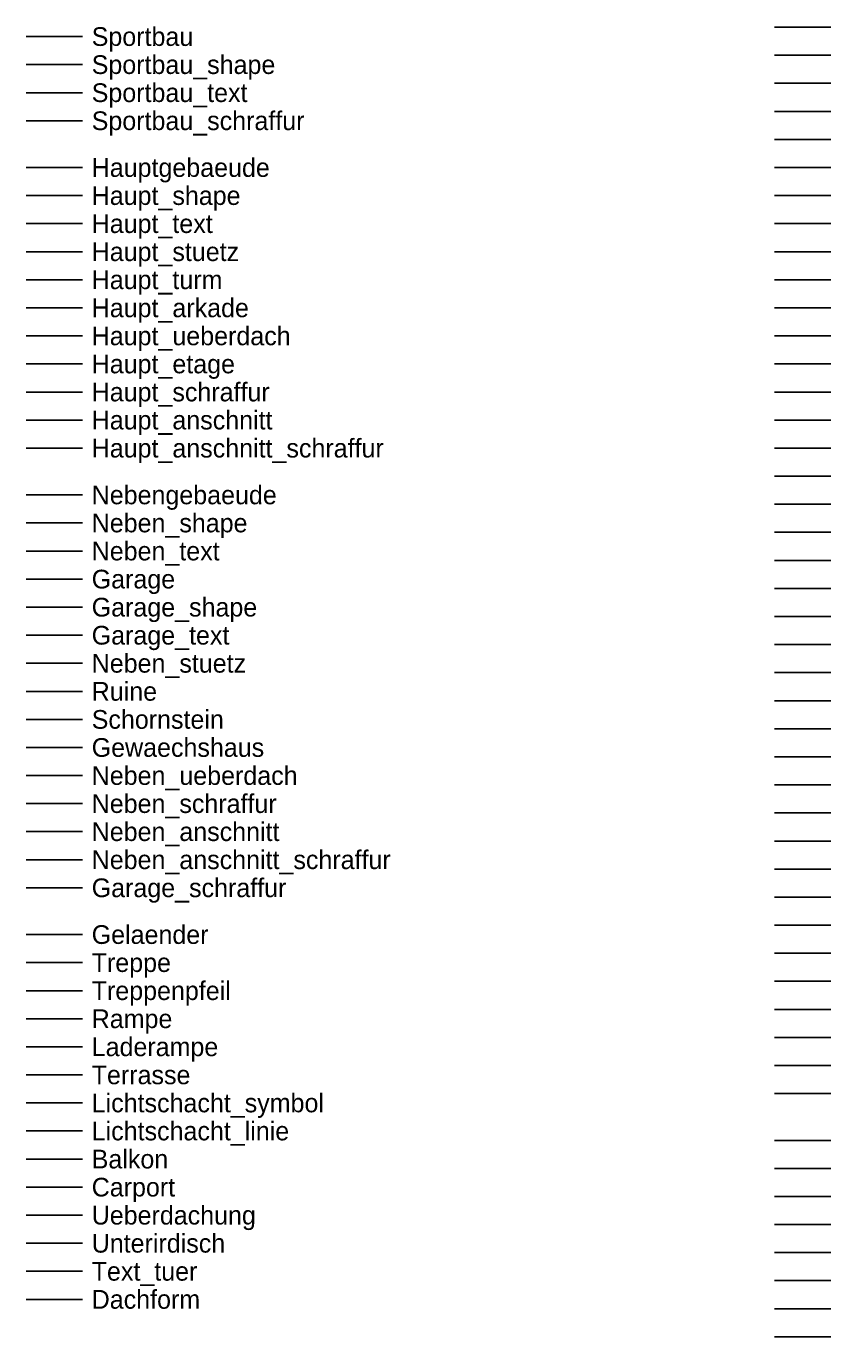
# Model space of a CAD drawing. Extents: x 0 to 177, y -135 to 1.
# Drawn here: x 0 to 43, y -134.5 to -64.4 of the extents above; entities that cross this region are included whole.
import ezdxf

# ---------------------------------------------------------------- set-up
doc = ezdxf.new("R2010")
doc.units = 0
for name, color, linetype in [('Anschlagsaeule', 7, 'Continuous'), ('Balkon', 7, 'Continuous'), ('Bank_linie', 7, 'Continuous'), ('Bank_symbol', 7, 'Continuous'), ('Befliegung_symbol', 7, 'Continuous'), ('Brandmelder', 7, 'Continuous'), ('Briefkasten', 7, 'Continuous'), ('Carport', 7, 'Continuous'), ('Dachform', 7, 'Continuous'), ('Denkmal', 7, 'Continuous'), ('Fahnenstange', 7, 'Continuous'), ('Fahrradstaender_linie', 7, 'Continuous'), ('Fahrradstaender_symbol', 7, 'Continuous'), ('Feuermelder', 7, 'Continuous'), ('Garage', 7, 'Continuous'), ('Garage_schraffur', 7, 'Continuous'), ('Garage_shape', 7, 'Continuous'), ('Garage_text', 7, 'Continuous'), ('Gelaender', 7, 'Continuous'), ('Gewaechshaus', 7, 'Continuous'), ('Haupt_anschnitt', 7, 'Continuous'), ('Haupt_anschnitt_schraffur', 7, 'Continuous'), ('Haupt_arkade', 7, 'Continuous'), ('Haupt_etage', 7, 'Continuous'), ('Haupt_schraffur', 7, 'Continuous'), ('Haupt_shape', 7, 'Continuous'), ('Haupt_stuetz', 7, 'Continuous'), ('Haupt_text', 7, 'Continuous'), ('Haupt_turm', 7, 'Continuous'), ('Haupt_ueberdach', 7, 'Continuous'), ('Hauptgebaeude', 7, 'Continuous'), ('Kaugummi', 7, 'Continuous'), ('Kilometerstein', 7, 'Continuous'), ('Kunst_linie', 7, 'Continuous'), ('Laderampe', 7, 'Continuous'), ('Leitpfosten', 7, 'Continuous'), ('Lichtschacht_linie', 7, 'Continuous'), ('Lichtschacht_symbol', 7, 'Continuous'), ('Mast_beton', 7, 'Continuous'), ('Mast_holz', 7, 'Continuous'), ('Mast_stahlgitter', 7, 'Continuous'), ('Mast_stahlrohr', 7, 'Continuous'), ('Merkstein', 7, 'Continuous'), ('Neben_anschnitt', 7, 'Continuous'), ('Neben_anschnitt_schraffur', 7, 'Continuous'), ('Neben_schraffur', 7, 'Continuous'), ('Neben_shape', 7, 'Continuous'), ('Neben_stuetz', 7, 'Continuous'), ('Neben_text', 7, 'Continuous'), ('Neben_ueberdach', 7, 'Continuous'), ('Nebengebaeude', 7, 'Continuous'), ('Notrufsaeule', 7, 'Continuous'), ('Ortstafel', 7, 'Continuous'), ('Papier_eckig', 7, 'Continuous'), ('Papier_rund', 7, 'Continuous'), ('Pfosten_beton', 7, 'Continuous'), ('Pfosten_holz', 7, 'Continuous'), ('Pfosten_metall', 7, 'Continuous'), ('Poller_eckig', 7, 'Continuous'), ('Poller_rund', 7, 'Continuous'), ('Rampe', 7, 'Continuous'), ('Ruine', 7, 'Continuous'), ('Schaltschrank', 7, 'Continuous'), ('Schieber', 7, 'Continuous'), ('Schildbruecke_linie', 7, 'Continuous'), ('Schildbruecke_symbol', 7, 'Continuous'), ('Schornstein', 7, 'Continuous'), ('Schranke_linie', 7, 'Continuous'), ('Schranke_symbol', 7, 'Continuous'), ('Sportbau', 7, 'Continuous'), ('Sportbau_schraffur', 7, 'Continuous'), ('Sportbau_shape', 7, 'Continuous'), ('Sportbau_text', 7, 'Continuous'), ('Terrasse', 7, 'Continuous'), ('Text_tuer', 7, 'Continuous'), ('Torpfosten_linie', 7, 'Continuous'), ('Treppe', 7, 'Continuous'), ('Treppenpfeil', 7, 'Continuous'), ('Ueberdachung', 7, 'Continuous'), ('Uhr', 7, 'Continuous'), ('Unterirdisch', 7, 'Continuous'), ('Verkehrszeichen', 7, 'Continuous'), ('Wegweiser', 7, 'Continuous'), ('Wegweiser_bel', 7, 'Continuous'), ('Werbetafel_linie', 7, 'Continuous'), ('Werbetafel_symbol', 7, 'Continuous'), ('Zaun_holz', 7, 'Continuous'), ('Zaun_metall', 7, 'Continuous'), ('Zaun_plaste', 7, 'Continuous'), ('Zauntor_text', 7, 'Continuous'), ('Zigaretten', 7, 'Continuous')]:
    doc.layers.add(name, color=color, linetype=linetype)

msp = doc.modelspace()

# ---------------------------------------------------------------- linework, layer by layer
at = {"layer": 'Anschlagsaeule'}
msp.add_line((40, -114), (43, -114), dxfattribs=at)
at = {"layer": 'Balkon'}
msp.add_line((0, -125), (3, -125), dxfattribs=at)
at = {"layer": 'Bank_linie'}
msp.add_line((40, -102), (43, -102), dxfattribs=at)
at = {"layer": 'Bank_symbol'}
msp.add_line((40, -100.5), (43, -100.5), dxfattribs=at)
at = {"layer": 'Befliegung_symbol'}
msp.add_line((40, -66), (43, -66), dxfattribs=at)
at = {"layer": 'Brandmelder'}
msp.add_line((40, -120), (43, -120), dxfattribs=at)
at = {"layer": 'Briefkasten'}
msp.add_line((40, -106.5), (43, -106.5), dxfattribs=at)
at = {"layer": 'Carport'}
msp.add_line((0, -126.5), (3, -126.5), dxfattribs=at)
at = {"layer": 'Dachform'}
msp.add_line((0, -132.5), (3, -132.5), dxfattribs=at)
at = {"layer": 'Denkmal'}
msp.add_line((40, -96), (43, -96), dxfattribs=at)
at = {"layer": 'Fahnenstange'}
msp.add_line((40, -79.5), (43, -79.5), dxfattribs=at)
at = {"layer": 'Fahrradstaender_linie'}
msp.add_line((40, -111), (43, -111), dxfattribs=at)
at = {"layer": 'Fahrradstaender_symbol'}
msp.add_line((40, -112.5), (43, -112.5), dxfattribs=at)
at = {"layer": 'Feuermelder'}
msp.add_line((40, -118.5), (43, -118.5), dxfattribs=at)
at = {"layer": 'Garage'}
msp.add_line((0, -94), (3, -94), dxfattribs=at)
at = {"layer": 'Garage_schraffur'}
msp.add_line((0, -110.5), (3, -110.5), dxfattribs=at)
at = {"layer": 'Garage_shape'}
msp.add_line((0, -95.5), (3, -95.5), dxfattribs=at)
at = {"layer": 'Garage_text'}
msp.add_line((0, -97), (3, -97), dxfattribs=at)
at = {"layer": 'Gelaender'}
msp.add_line((0, -113), (3, -113), dxfattribs=at)
at = {"layer": 'Gewaechshaus'}
msp.add_line((0, -103), (3, -103), dxfattribs=at)
at = {"layer": 'Haupt_anschnitt'}
msp.add_line((0, -85.5), (3, -85.5), dxfattribs=at)
at = {"layer": 'Haupt_anschnitt_schraffur'}
msp.add_line((0, -87), (3, -87), dxfattribs=at)
at = {"layer": 'Haupt_arkade'}
msp.add_line((0, -79.5), (3, -79.5), dxfattribs=at)
at = {"layer": 'Haupt_etage'}
msp.add_line((0, -82.5), (3, -82.5), dxfattribs=at)
at = {"layer": 'Haupt_schraffur'}
msp.add_line((0, -84), (3, -84), dxfattribs=at)
at = {"layer": 'Haupt_shape'}
msp.add_line((0, -73.5), (3, -73.5), dxfattribs=at)
at = {"layer": 'Haupt_stuetz'}
msp.add_line((0, -76.5), (3, -76.5), dxfattribs=at)
at = {"layer": 'Haupt_text'}
msp.add_line((0, -75), (3, -75), dxfattribs=at)
at = {"layer": 'Haupt_turm'}
msp.add_line((0, -78), (3, -78), dxfattribs=at)
at = {"layer": 'Haupt_ueberdach'}
msp.add_line((0, -81), (3, -81), dxfattribs=at)
at = {"layer": 'Hauptgebaeude'}
msp.add_line((0, -72), (3, -72), dxfattribs=at)
at = {"layer": 'Kaugummi'}
msp.add_line((40, -109.5), (43, -109.5), dxfattribs=at)
at = {"layer": 'Kilometerstein'}
msp.add_line((40, -78), (43, -78), dxfattribs=at)
at = {"layer": 'Kunst_linie'}
msp.add_line((40, -97.5), (43, -97.5), dxfattribs=at)
at = {"layer": 'Laderampe'}
msp.add_line((0, -119), (3, -119), dxfattribs=at)
at = {"layer": 'Leitpfosten'}
msp.add_line((40, -82.5), (43, -82.5), dxfattribs=at)
at = {"layer": 'Lichtschacht_linie'}
msp.add_line((0, -123.5), (3, -123.5), dxfattribs=at)
at = {"layer": 'Lichtschacht_symbol'}
msp.add_line((0, -122), (3, -122), dxfattribs=at)
at = {"layer": 'Mast_beton'}
msp.add_line((40, -84), (43, -84), dxfattribs=at)
at = {"layer": 'Mast_holz'}
msp.add_line((40, -85.5), (43, -85.5), dxfattribs=at)
at = {"layer": 'Mast_stahlgitter'}
msp.add_line((40, -88.5), (43, -88.5), dxfattribs=at)
at = {"layer": 'Mast_stahlrohr'}
msp.add_line((40, -87), (43, -87), dxfattribs=at)
at = {"layer": 'Merkstein'}
msp.add_line((40, -64.5), (43, -64.5), dxfattribs=at)
at = {"layer": 'Neben_anschnitt'}
msp.add_line((0, -107.5), (3, -107.5), dxfattribs=at)
at = {"layer": 'Neben_anschnitt_schraffur'}
msp.add_line((0, -109), (3, -109), dxfattribs=at)
at = {"layer": 'Neben_schraffur'}
msp.add_line((0, -106), (3, -106), dxfattribs=at)
at = {"layer": 'Neben_shape'}
msp.add_line((0, -91), (3, -91), dxfattribs=at)
at = {"layer": 'Neben_stuetz'}
msp.add_line((0, -98.5), (3, -98.5), dxfattribs=at)
at = {"layer": 'Neben_text'}
msp.add_line((0, -92.5), (3, -92.5), dxfattribs=at)
at = {"layer": 'Neben_ueberdach'}
msp.add_line((0, -104.5), (3, -104.5), dxfattribs=at)
at = {"layer": 'Nebengebaeude'}
msp.add_line((0, -89.5), (3, -89.5), dxfattribs=at)
at = {"layer": 'Notrufsaeule'}
msp.add_line((40, -121.5), (43, -121.5), dxfattribs=at)
at = {"layer": 'Ortstafel'}
msp.add_line((40, -76.5), (43, -76.5), dxfattribs=at)
at = {"layer": 'Papier_eckig'}
msp.add_line((40, -105), (43, -105), dxfattribs=at)
at = {"layer": 'Papier_rund'}
msp.add_line((40, -103.5), (43, -103.5), dxfattribs=at)
at = {"layer": 'Pfosten_beton'}
msp.add_line((40, -128.5), (43, -128.5), dxfattribs=at)
at = {"layer": 'Pfosten_holz'}
msp.add_line((40, -130), (43, -130), dxfattribs=at)
at = {"layer": 'Pfosten_metall'}
msp.add_line((40, -131.5), (43, -131.5), dxfattribs=at)
at = {"layer": 'Poller_eckig'}
msp.add_line((40, -94.5), (43, -94.5), dxfattribs=at)
at = {"layer": 'Poller_rund'}
msp.add_line((40, -93), (43, -93), dxfattribs=at)
at = {"layer": 'Rampe'}
msp.add_line((0, -117.5), (3, -117.5), dxfattribs=at)
at = {"layer": 'Ruine'}
msp.add_line((0, -100), (3, -100), dxfattribs=at)
at = {"layer": 'Schaltschrank'}
msp.add_line((40, -81), (43, -81), dxfattribs=at)
at = {"layer": 'Schieber'}
msp.add_line((40, -67.5), (43, -67.5), dxfattribs=at)
at = {"layer": 'Schildbruecke_linie'}
msp.add_line((40, -70.5), (43, -70.5), dxfattribs=at)
at = {"layer": 'Schildbruecke_symbol'}
msp.add_line((40, -72), (43, -72), dxfattribs=at)
at = {"layer": 'Schornstein'}
msp.add_line((0, -101.5), (3, -101.5), dxfattribs=at)
at = {"layer": 'Schranke_linie'}
msp.add_line((40, -90), (43, -90), dxfattribs=at)
at = {"layer": 'Schranke_symbol'}
msp.add_line((40, -91.5), (43, -91.5), dxfattribs=at)
at = {"layer": 'Sportbau'}
msp.add_line((0, -65), (3, -65), dxfattribs=at)
at = {"layer": 'Sportbau_schraffur'}
msp.add_line((0, -69.5), (3, -69.5), dxfattribs=at)
at = {"layer": 'Sportbau_shape'}
msp.add_line((0, -66.5), (3, -66.5), dxfattribs=at)
at = {"layer": 'Sportbau_text'}
msp.add_line((0, -68), (3, -68), dxfattribs=at)
at = {"layer": 'Terrasse'}
msp.add_line((0, -120.5), (3, -120.5), dxfattribs=at)
at = {"layer": 'Text_tuer'}
msp.add_line((0, -131), (3, -131), dxfattribs=at)
at = {"layer": 'Torpfosten_linie'}
msp.add_line((40, -133), (43, -133), dxfattribs=at)
at = {"layer": 'Treppe'}
msp.add_line((0, -114.5), (3, -114.5), dxfattribs=at)
at = {"layer": 'Treppenpfeil'}
msp.add_line((0, -116), (3, -116), dxfattribs=at)
at = {"layer": 'Ueberdachung'}
msp.add_line((0, -128), (3, -128), dxfattribs=at)
at = {"layer": 'Uhr'}
msp.add_line((40, -99), (43, -99), dxfattribs=at)
at = {"layer": 'Unterirdisch'}
msp.add_line((0, -129.5), (3, -129.5), dxfattribs=at)
at = {"layer": 'Verkehrszeichen'}
msp.add_line((40, -69), (43, -69), dxfattribs=at)
at = {"layer": 'Wegweiser'}
msp.add_line((40, -73.5), (43, -73.5), dxfattribs=at)
at = {"layer": 'Wegweiser_bel'}
msp.add_line((40, -75), (43, -75), dxfattribs=at)
at = {"layer": 'Werbetafel_linie'}
msp.add_line((40, -115.5), (43, -115.5), dxfattribs=at)
at = {"layer": 'Werbetafel_symbol'}
msp.add_line((40, -117), (43, -117), dxfattribs=at)
at = {"layer": 'Zaun_holz'}
msp.add_line((40, -124), (43, -124), dxfattribs=at)
at = {"layer": 'Zaun_metall'}
msp.add_line((40, -125.5), (43, -125.5), dxfattribs=at)
at = {"layer": 'Zaun_plaste'}
msp.add_line((40, -127), (43, -127), dxfattribs=at)
at = {"layer": 'Zauntor_text'}
msp.add_line((40, -134.5), (43, -134.5), dxfattribs=at)
at = {"layer": 'Zigaretten'}
msp.add_line((40, -108), (43, -108), dxfattribs=at)

# ---------------------------------------------------------------- texts
at = {"layer": 'Balkon'}
msp.add_text('Balkon', height=1, dxfattribs=at).set_placement((3.5, -125.5))
at = {"layer": 'Carport'}
msp.add_text('Carport', height=1, dxfattribs=at).set_placement((3.5, -127))
at = {"layer": 'Dachform'}
msp.add_text('Dachform', height=1, dxfattribs=at).set_placement((3.5, -133))
at = {"layer": 'Garage'}
msp.add_text('Garage', height=1, dxfattribs=at).set_placement((3.5, -94.5))
at = {"layer": 'Garage_schraffur'}
msp.add_text('Garage_schraffur', height=1, dxfattribs=at).set_placement((3.5, -111))
at = {"layer": 'Garage_shape'}
msp.add_text('Garage_shape', height=1, dxfattribs=at).set_placement((3.5, -96))
at = {"layer": 'Garage_text'}
msp.add_text('Garage_text', height=1, dxfattribs=at).set_placement((3.5, -97.5))
at = {"layer": 'Gelaender'}
msp.add_text('Gelaender', height=1, dxfattribs=at).set_placement((3.5, -113.5))
at = {"layer": 'Gewaechshaus'}
msp.add_text('Gewaechshaus', height=1, dxfattribs=at).set_placement((3.5, -103.5))
at = {"layer": 'Haupt_anschnitt'}
msp.add_text('Haupt_anschnitt', height=1, dxfattribs=at).set_placement((3.5, -86))
at = {"layer": 'Haupt_anschnitt_schraffur'}
msp.add_text('Haupt_anschnitt_schraffur', height=1, dxfattribs=at).set_placement((3.5, -87.5))
at = {"layer": 'Haupt_arkade'}
msp.add_text('Haupt_arkade', height=1, dxfattribs=at).set_placement((3.5, -80))
at = {"layer": 'Haupt_etage'}
msp.add_text('Haupt_etage', height=1, dxfattribs=at).set_placement((3.5, -83))
at = {"layer": 'Haupt_schraffur'}
msp.add_text('Haupt_schraffur', height=1, dxfattribs=at).set_placement((3.5, -84.5))
at = {"layer": 'Haupt_shape'}
msp.add_text('Haupt_shape', height=1, dxfattribs=at).set_placement((3.5, -74))
at = {"layer": 'Haupt_stuetz'}
msp.add_text('Haupt_stuetz', height=1, dxfattribs=at).set_placement((3.5, -77))
at = {"layer": 'Haupt_text'}
msp.add_text('Haupt_text', height=1, dxfattribs=at).set_placement((3.5, -75.5))
at = {"layer": 'Haupt_turm'}
msp.add_text('Haupt_turm', height=1, dxfattribs=at).set_placement((3.5, -78.5))
at = {"layer": 'Haupt_ueberdach'}
msp.add_text('Haupt_ueberdach', height=1, dxfattribs=at).set_placement((3.5, -81.5))
at = {"layer": 'Hauptgebaeude'}
msp.add_text('Hauptgebaeude', height=1, dxfattribs=at).set_placement((3.5, -72.5))
at = {"layer": 'Laderampe'}
msp.add_text('Laderampe', height=1, dxfattribs=at).set_placement((3.5, -119.5))
at = {"layer": 'Lichtschacht_linie'}
msp.add_text('Lichtschacht_linie', height=1, dxfattribs=at).set_placement((3.5, -124))
at = {"layer": 'Lichtschacht_symbol'}
msp.add_text('Lichtschacht_symbol', height=1, dxfattribs=at).set_placement((3.5, -122.5))
at = {"layer": 'Neben_anschnitt'}
msp.add_text('Neben_anschnitt', height=1, dxfattribs=at).set_placement((3.5, -108))
at = {"layer": 'Neben_anschnitt_schraffur'}
msp.add_text('Neben_anschnitt_schraffur', height=1, dxfattribs=at).set_placement((3.5, -109.5))
at = {"layer": 'Neben_schraffur'}
msp.add_text('Neben_schraffur', height=1, dxfattribs=at).set_placement((3.5, -106.5))
at = {"layer": 'Neben_shape'}
msp.add_text('Neben_shape', height=1, dxfattribs=at).set_placement((3.5, -91.5))
at = {"layer": 'Neben_stuetz'}
msp.add_text('Neben_stuetz', height=1, dxfattribs=at).set_placement((3.5, -99))
at = {"layer": 'Neben_text'}
msp.add_text('Neben_text', height=1, dxfattribs=at).set_placement((3.5, -93))
at = {"layer": 'Neben_ueberdach'}
msp.add_text('Neben_ueberdach', height=1, dxfattribs=at).set_placement((3.5, -105))
at = {"layer": 'Nebengebaeude'}
msp.add_text('Nebengebaeude', height=1, dxfattribs=at).set_placement((3.5, -90))
at = {"layer": 'Rampe'}
msp.add_text('Rampe', height=1, dxfattribs=at).set_placement((3.5, -118))
at = {"layer": 'Ruine'}
msp.add_text('Ruine', height=1, dxfattribs=at).set_placement((3.5, -100.5))
at = {"layer": 'Schornstein'}
msp.add_text('Schornstein', height=1, dxfattribs=at).set_placement((3.5, -102))
at = {"layer": 'Sportbau'}
msp.add_text('Sportbau', height=1, dxfattribs=at).set_placement((3.5, -65.5))
at = {"layer": 'Sportbau_schraffur'}
msp.add_text('Sportbau_schraffur', height=1, dxfattribs=at).set_placement((3.5, -70))
at = {"layer": 'Sportbau_shape'}
msp.add_text('Sportbau_shape', height=1, dxfattribs=at).set_placement((3.5, -67))
at = {"layer": 'Sportbau_text'}
msp.add_text('Sportbau_text', height=1, dxfattribs=at).set_placement((3.5, -68.5))
at = {"layer": 'Terrasse'}
msp.add_text('Terrasse', height=1, dxfattribs=at).set_placement((3.5, -121))
at = {"layer": 'Text_tuer'}
msp.add_text('Text_tuer', height=1, dxfattribs=at).set_placement((3.5, -131.5))
at = {"layer": 'Treppe'}
msp.add_text('Treppe', height=1, dxfattribs=at).set_placement((3.5, -115))
at = {"layer": 'Treppenpfeil'}
msp.add_text('Treppenpfeil', height=1, dxfattribs=at).set_placement((3.5, -116.5))
at = {"layer": 'Ueberdachung'}
msp.add_text('Ueberdachung', height=1, dxfattribs=at).set_placement((3.5, -128.5))
at = {"layer": 'Unterirdisch'}
msp.add_text('Unterirdisch', height=1, dxfattribs=at).set_placement((3.5, -130))

doc.saveas('drawing.dxf')
